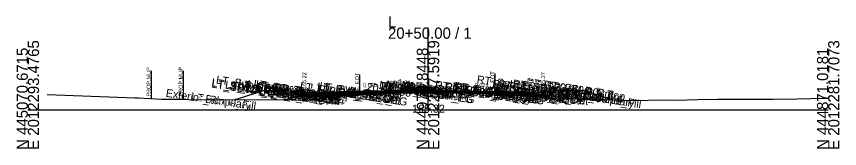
# Model space of a CAD drawing. Extents: x -26 to 4203, y -10 to 9526.
# Drawn here: x 997.2 to 1202.8, y 490.3 to 523.5 of the extents above; entities that cross this region are included whole.
import ezdxf

# ---------------------------------------------------------------- set-up
doc = ezdxf.new("R2010")
doc.units = 0
for name, color, linetype in [('Default', 7, 'Continuous'), ('Exist CMT Pavement', 7, 'Continuous'), ('Exist Cross Section Cell', 7, 'Continuous'), ('Exist XS Center Line Elevation Label', 7, 'Continuous'), ('Exist XS Ground Line', 7, 'Continuous'), ('Prop CMT Conc Surface', 7, 'Continuous'), ('Prop CMT Concrete Structures', 7, 'Continuous'), ('Prop CMT Pvmt Course 1', 7, 'Continuous'), ('Prop CMT Pvmt Course 1 CG', 7, 'Continuous'), ('Prop CMT Pvmt Course 1 Wedge', 7, 'Continuous'), ('Prop CMT Pvmt Course 2', 7, 'Continuous'), ('Prop CMT Pvmt Course 2 Wedge', 7, 'Continuous'), ('Prop CMT Pvmt Course 3', 7, 'Continuous'), ('Prop CMT Pvmt Course 3 Wedge', 7, 'Continuous'), ('Prop CMT Pvmt Surface', 7, 'Continuous'), ('Prop CMT Pvmt Wedge Surface 1', 7, 'Continuous'), ('Prop CMT Pvmt Wedge Surface 2', 7, 'Continuous'), ('Prop CMT Pvmt Wedge Surface 3', 7, 'Continuous'), ('Prop CMT Slope Grass', 7, 'Continuous'), ('Prop CMT Subgrade Earthwork', 7, 'Continuous'), ('Prop XS Hydro Elevations', 7, 'Continuous'), ('Prop XS Label Text', 7, 'Continuous'), ('Prop XS SE Text', 7, 'Continuous'), ('Prop XS Side Slope Text', 7, 'Continuous'), ('Scratch_Level_0', 7, 'Continuous')]:
    doc.layers.add(name, color=color, linetype=linetype)

msp = doc.modelspace()

# ---------------------------------------------------------------- linework, layer by layer
at = {"layer": 'Exist CMT Pavement'}
for points in [[(1100, 504.32), (1098.93, 504.32), (1098.29, 504.32), (1096.56, 504.29), (1095.78, 504.28), (1094.34, 504.26), (1093.69, 504.26), (1093.52, 504.26), (1093.28, 504.25), (1092.26, 504.21), (1090.78, 504.15), (1089.59, 504.1), (1088.28, 504.05), (1087.1, 503.97), (1085.76, 503.87), (1084.71, 503.85), (1082.9, 503.79)], [(1100, 504.32), (1100.79, 504.32), (1101.29, 504.32), (1103.29, 504.32), (1103.62, 504.32), (1104.82, 504.32), (1105.68, 504.31), (1105.79, 504.31), (1106.01, 504.31), (1108.3, 504.27), (1108.37, 504.27), (1109.65, 504.26), (1110.81, 504.24), (1110.88, 504.24), (1113.32, 504.19), (1113.56, 504.19), (1115.82, 504.14), (1115.89, 504.14), (1116.71, 504.14)], [(1082.9, 503.79), (1082.9, 503.79)]]:
    msp.add_lwpolyline(points, dxfattribs=at)
at = {"layer": 'Exist Cross Section Cell'}
for p, q in [((1100, 500), (1100, 520.65)), ((1000, 500), (1100, 500)), ((1100, 500), (1200, 500))]:
    msp.add_line(p, q, dxfattribs=at)
at = {"layer": 'Exist XS Ground Line'}
msp.add_lwpolyline([(1004.81, 503.84), (1026.81, 503.01), (1027.6, 503), (1033.38, 502.73), (1038.28, 502.67), (1040.26, 502.64), (1065.9, 502.52), (1068.93, 502.44), (1069.48, 502.47), (1071.16, 502.65), (1074.84, 503.03), (1081.1, 503.68), (1082.9, 503.79), (1084.71, 503.85), (1085.76, 503.87), (1087.1, 503.97), (1088.28, 504.05), (1089.59, 504.1), (1090.78, 504.15), (1092.26, 504.21), (1093.69, 504.26), (1094.34, 504.26), (1095.78, 504.28), (1096.56, 504.29), (1098.29, 504.32), (1098.93, 504.32), (1100, 504.32), (1100.79, 504.32), (1101.29, 504.32), (1103.29, 504.32), (1103.62, 504.32), (1104.82, 504.32), (1106.01, 504.31), (1108.37, 504.27), (1109.65, 504.26), (1110.88, 504.24), (1113.56, 504.19), (1115.89, 504.14), (1116.71, 504.14), (1125, 503.43), (1132.16, 502.87), (1138.93, 502.78), (1142.17, 502.7), (1148.39, 502.41), (1152.19, 502.34), (1157.85, 502.51), (1162.21, 502.47), (1167.31, 502.58), (1172.23, 502.74), (1176.77, 502.74), (1182.25, 502.69), (1186.23, 502.68), (1192.27, 502.8), (1195.69, 502.89), (1200, 502.95)], dxfattribs=at)
at = {"layer": 'Prop CMT Conc Surface'}
for points in [[(1069.06, 504.22), (1069.06, 504.72), (1068.56, 504.72)], [(1071.06, 504.35), (1069.06, 504.22)], [(1126.75, 504.4), (1128.75, 504.27)], [(1128.75, 504.27), (1128.75, 504.77), (1129.25, 504.77)], [(1133.25, 504.86), (1138.25, 504.96)]]:
    msp.add_lwpolyline(points, dxfattribs=at)
at = {"layer": 'Prop CMT Concrete Structures'}
for points in [[(1071.06, 504.35), (1069.06, 504.22), (1069.06, 504.72), (1068.56, 504.72)], [(1068.56, 504.72), (1068.56, 503.7), (1071.06, 503.76)], [(1071.06, 503.76), (1071.06, 504.35)], [(1102, 505.02), (1101.99, 505.19), (1101.24, 505.44), (1098.92, 505.48), (1096.59, 505.38), (1095.84, 505.13), (1095.83, 504.96)], [(1095.83, 504.96), (1100, 505.07), (1102, 505.02)], [(1126.75, 504.4), (1128.75, 504.27), (1128.75, 504.77), (1129.25, 504.77)], [(1129.25, 504.77), (1129.25, 503.76), (1126.75, 503.82)], [(1126.75, 503.82), (1126.75, 504.4)], [(1138.25, 504.96), (1133.25, 504.86)], [(1133.25, 504.86), (1133.25, 504.53)], [(1133.25, 504.53), (1138.25, 504.63)], [(1138.25, 504.63), (1138.25, 504.96)]]:
    msp.add_lwpolyline(points, dxfattribs=at)
at = {"layer": 'Prop CMT Pvmt Course 1'}
for points in [[(1100, 505.07), (1071.06, 504.35)], [(1071.06, 504.1), (1082.9, 504.39)], [(1071.06, 504.35), (1071.06, 504.1)], [(1082.9, 504.52), (1100, 504.94)], [(1082.9, 504.39), (1082.9, 504.52)], [(1100, 504.82), (1100, 505.07)], [(1100, 505.07), (1126.75, 504.4)], [(1100, 504.82), (1100, 505.07)], [(1100, 504.94), (1100, 504.82), (1100, 504.82)], [(1116.71, 504.53), (1100, 504.94)], [(1100, 504.94), (1100, 504.82), (1100, 504.82)], [(1116.71, 504.4), (1116.71, 504.53)], [(1126.75, 504.15), (1116.71, 504.4)], [(1126.75, 504.4), (1126.75, 504.15)]]:
    msp.add_lwpolyline(points, dxfattribs=at)
at = {"layer": 'Prop CMT Pvmt Course 1 CG'}
for points in [[(1071.06, 503.76), (1068.06, 503.69), (1067.72, 503.35)], [(1067.72, 503.35), (1071.06, 503.43)], [(1071.06, 503.43), (1071.06, 503.76)], [(1126.75, 503.82), (1129.75, 503.74), (1130.09, 503.4)], [(1126.75, 503.48), (1126.75, 503.82)], [(1130.09, 503.4), (1126.75, 503.48)]]:
    msp.add_lwpolyline(points, dxfattribs=at)
at = {"layer": 'Prop CMT Pvmt Course 1 Wedge'}
for points in [[(1082.9, 504.52), (1083, 504.52), (1084.71, 504.56), (1085.76, 504.59), (1087.1, 504.62), (1088.28, 504.65), (1089.59, 504.68), (1090.78, 504.71), (1092.26, 504.75), (1093.28, 504.78), (1093.52, 504.78), (1093.69, 504.79), (1094.34, 504.8), (1095.78, 504.84), (1096.56, 504.86), (1098.29, 504.9), (1098.93, 504.92), (1100, 504.94)], [(1100, 504.82), (1098.93, 504.79), (1098.29, 504.78), (1096.56, 504.73), (1095.78, 504.71), (1094.34, 504.68), (1093.69, 504.66), (1093.52, 504.66), (1093.28, 504.65), (1092.26, 504.63), (1090.78, 504.59), (1089.59, 504.56), (1088.28, 504.53), (1087.1, 504.5), (1085.76, 504.46), (1084.71, 504.44), (1083, 504.39), (1082.9, 504.39)], [(1082.9, 504.52), (1082.9, 504.52)], [(1082.9, 504.39), (1082.9, 504.52)], [(1082.9, 504.39), (1082.9, 504.39)], [(1100, 504.94), (1100, 504.82)], [(1100, 504.94), (1100.79, 504.92), (1101.29, 504.91), (1103.29, 504.86), (1103.62, 504.85), (1104.82, 504.82), (1105.68, 504.8), (1105.79, 504.8), (1106.01, 504.79), (1108.3, 504.74), (1108.37, 504.74), (1109.65, 504.7), (1110.81, 504.67), (1110.88, 504.67), (1113.32, 504.61), (1113.56, 504.61), (1115.82, 504.55), (1115.89, 504.55), (1116.71, 504.53)], [(1100, 504.82), (1100, 504.94)], [(1116.71, 504.4), (1115.89, 504.42), (1115.82, 504.42), (1113.56, 504.48), (1113.32, 504.49), (1110.88, 504.55), (1110.81, 504.55), (1109.65, 504.58), (1108.37, 504.61), (1108.3, 504.61), (1106.01, 504.67), (1105.79, 504.67), (1105.68, 504.68), (1104.82, 504.7), (1103.62, 504.73), (1103.29, 504.74), (1101.29, 504.79), (1100.79, 504.8), (1100, 504.82)], [(1116.71, 504.53), (1116.71, 504.4)]]:
    msp.add_lwpolyline(points, dxfattribs=at)
at = {"layer": 'Prop CMT Pvmt Course 2'}
for points in [[(1082.9, 504.39), (1071.06, 504.1)], [(1071.06, 504.1), (1071.06, 503.76)], [(1071.06, 503.76), (1082.9, 504.06)], [(1082.9, 504.06), (1082.9, 504.39)], [(1116.71, 504.07), (1116.71, 504.4)], [(1116.71, 504.4), (1126.75, 504.15)], [(1126.75, 503.82), (1116.71, 504.07)], [(1126.75, 504.15), (1126.75, 503.82)]]:
    msp.add_lwpolyline(points, dxfattribs=at)
at = {"layer": 'Prop CMT Pvmt Course 2 Wedge'}
for points in [[(1082.9, 504.39), (1083, 504.39), (1084.71, 504.44), (1085.76, 504.46), (1087.1, 504.5), (1088.28, 504.53), (1089.59, 504.56), (1090.78, 504.59), (1092.26, 504.63), (1093.28, 504.65), (1093.52, 504.66), (1093.69, 504.66), (1094.34, 504.68), (1095.78, 504.71), (1096.56, 504.73), (1098.29, 504.78), (1098.93, 504.79), (1100, 504.82)], [(1100, 504.49), (1098.93, 504.46), (1098.29, 504.44), (1096.56, 504.4), (1095.78, 504.38), (1094.34, 504.34), (1093.69, 504.33), (1093.52, 504.32), (1093.28, 504.32), (1092.26, 504.29), (1090.78, 504.26), (1089.59, 504.23), (1088.28, 504.19), (1087.1, 504.16), (1085.76, 504.13), (1084.71, 504.1), (1083, 504.06), (1082.9, 504.06)], [(1082.9, 504.39), (1082.9, 504.39)], [(1082.9, 504.06), (1082.9, 504.39)], [(1082.9, 504.06), (1082.9, 504.06)], [(1100, 504.82), (1100.79, 504.8), (1101.29, 504.79), (1103.29, 504.74), (1103.62, 504.73), (1104.82, 504.7), (1105.68, 504.68), (1105.79, 504.67), (1106.01, 504.67), (1108.3, 504.61), (1108.37, 504.61), (1109.65, 504.58), (1110.81, 504.55), (1110.88, 504.55), (1113.32, 504.49), (1113.56, 504.48), (1115.82, 504.42), (1115.89, 504.42), (1116.71, 504.4)], [(1100, 504.49), (1100, 504.82)], [(1100, 504.82), (1100, 504.49)], [(1116.71, 504.14), (1115.89, 504.14), (1115.82, 504.14), (1113.56, 504.19), (1113.32, 504.19), (1110.88, 504.24), (1110.81, 504.24), (1109.65, 504.26), (1108.94, 504.26), (1108.37, 504.28), (1108.3, 504.28), (1106.01, 504.34), (1105.79, 504.34), (1105.68, 504.34), (1104.82, 504.37), (1103.62, 504.4), (1103.29, 504.4), (1101.29, 504.45), (1100.79, 504.47), (1100, 504.49)], [(1116.71, 504.4), (1116.71, 504.14)]]:
    msp.add_lwpolyline(points, dxfattribs=at)
at = {"layer": 'Prop CMT Pvmt Course 3'}
for points in [[(1082.9, 504.06), (1071.06, 503.76)], [(1082.9, 503.72), (1082.9, 504.06)], [(1116.71, 504.07), (1126.75, 503.82)], [(1116.71, 503.74), (1116.71, 504.07)], [(1071.06, 503.76), (1071.06, 503.43)], [(1071.06, 503.43), (1082.9, 503.72)], [(1126.75, 503.48), (1116.71, 503.74)], [(1126.75, 503.82), (1126.75, 503.48)]]:
    msp.add_lwpolyline(points, dxfattribs=at)
at = {"layer": 'Prop CMT Pvmt Course 3 Wedge'}
for points in [[(1082.9, 504.06), (1083, 504.06), (1084.71, 504.1), (1085.76, 504.13), (1087.1, 504.16), (1088.28, 504.19), (1089.59, 504.23), (1090.78, 504.26), (1092.26, 504.29), (1093.28, 504.32), (1093.52, 504.32), (1093.69, 504.33), (1094.34, 504.34), (1095.78, 504.38), (1096.56, 504.4), (1098.29, 504.44), (1098.93, 504.46), (1100, 504.49)], [(1100, 504.32), (1098.93, 504.32), (1098.29, 504.32), (1096.56, 504.29), (1095.78, 504.28), (1094.34, 504.26), (1093.69, 504.26), (1093.52, 504.26), (1093.28, 504.25), (1092.26, 504.21), (1090.78, 504.15), (1089.59, 504.1), (1088.28, 504.05), (1087.1, 503.97), (1085.76, 503.87), (1084.71, 503.85), (1082.9, 503.79)], [(1082.9, 504.06), (1082.9, 504.06)], [(1082.9, 503.79), (1082.9, 504.06)], [(1100, 504.49), (1100.79, 504.47), (1101.29, 504.45), (1103.29, 504.4), (1103.62, 504.4), (1104.82, 504.37), (1105.68, 504.34), (1105.79, 504.34), (1106.01, 504.34), (1108.3, 504.28), (1108.37, 504.28), (1108.93, 504.26)], [(1100, 504.32), (1100, 504.49)], [(1100, 504.49), (1100, 504.32)], [(1108.93, 504.26), (1108.37, 504.27), (1108.3, 504.27), (1106.01, 504.31), (1105.79, 504.31), (1105.68, 504.31), (1104.82, 504.32), (1103.62, 504.32), (1103.29, 504.32), (1101.29, 504.32), (1100.79, 504.32), (1100, 504.32)], [(1082.9, 503.79), (1082.9, 503.79)]]:
    msp.add_lwpolyline(points, dxfattribs=at)
at = {"layer": 'Prop CMT Pvmt Surface'}
for points in [[(1100, 505.07), (1071.06, 504.35)], [(1100, 505.07), (1126.75, 504.4)]]:
    msp.add_lwpolyline(points, dxfattribs=at)
at = {"layer": 'Prop CMT Pvmt Wedge Surface 1'}
for points in [[(1082.9, 504.39), (1071.06, 504.1)], [(1071.06, 504.1), (1071.06, 504.35)], [(1100, 504.94), (1082.9, 504.52)], [(1082.9, 504.52), (1082.9, 504.39)], [(1100, 504.94), (1116.71, 504.53)], [(1116.71, 504.53), (1116.71, 504.4)], [(1116.71, 504.4), (1126.75, 504.15)], [(1126.75, 504.15), (1126.75, 504.4)]]:
    msp.add_lwpolyline(points, dxfattribs=at)
at = {"layer": 'Prop CMT Pvmt Wedge Surface 2'}
for points in [[(1100, 504.82), (1071.06, 504.1)], [(1071.06, 504.1), (1071.06, 504.35)], [(1100, 504.82), (1126.75, 504.15)], [(1126.75, 504.15), (1126.75, 504.4)]]:
    msp.add_lwpolyline(points, dxfattribs=at)
at = {"layer": 'Prop CMT Pvmt Wedge Surface 3'}
for points in [[(1100, 504.49), (1071.06, 503.76)], [(1071.06, 503.76), (1071.06, 504.35)], [(1100, 504.49), (1126.75, 503.82)], [(1126.75, 503.82), (1126.75, 504.4)]]:
    msp.add_lwpolyline(points, dxfattribs=at)
at = {"layer": 'Prop CMT Slope Grass'}
for points in [[(1068.56, 504.72), (1059.06, 504.91), (1052.1, 502.59)], [(1129.25, 504.77), (1138.75, 504.96), (1146.09, 502.52)]]:
    msp.add_lwpolyline(points, dxfattribs=at)
at = {"layer": 'Prop CMT Subgrade Earthwork'}
for points in [[(1071.06, 503.43), (1067.72, 503.35), (1066.3, 504.76)], [(1116.71, 503.74), (1116.71, 504.14)], [(1126.75, 503.48), (1130.09, 503.4), (1131.51, 504.82)], [(1082.9, 503.72), (1071.06, 503.43)], [(1082.9, 503.72), (1082.9, 503.79)], [(1116.71, 503.74), (1126.75, 503.48)]]:
    msp.add_lwpolyline(points, dxfattribs=at)
at = {"layer": 'Prop XS Label Text'}
for p, q in [((1030.79, 509.78), (1030.79, 502.78)), ((1038.81, 509.8), (1038.81, 502.8)), ((1082.9, 508.79), (1082.9, 503.79)), ((1116.71, 509.14), (1116.71, 504.14))]:
    msp.add_line(p, q, dxfattribs=at)

# ---------------------------------------------------------------- texts
at = {"layer": 'Default'}
msp.add_text('-', height=0.0001, dxfattribs=at).set_placement((1000, 500))
at = {"layer": 'Exist Cross Section Cell'}
for s, p in [('L', (1090, 520.65)), ('20+50.00 / 1', (1090, 517.85))]:
    msp.add_text(s, height=2.8, dxfattribs=at).set_placement(p)
for s, p in [('E 2012293.4765', (1002.8, 490)), ('E 2012287.5919', (1102.8, 490)), ('E 2012281.7073', (1202.8, 490)), ('N 445070.6715', (1000, 490)), ('N 444970.8448', (1100, 490)), ('N 444871.0181', (1200, 490))]:
    msp.add_text(s, height=2.8, rotation=90, dxfattribs=at).set_placement(p)
at = {"layer": 'Exist XS Center Line Elevation Label'}
msp.add_text('165.32', height=2, dxfattribs=at).set_placement((1096.03, 499.32))
at = {"layer": 'Prop XS Hydro Elevations'}
for s, p in [('165.22', (1069.56, 505.22)), ('165.27', (1129.25, 505.27))]:
    msp.add_text(s, height=1, rotation=90, dxfattribs=at).set_placement(p)
at = {"layer": 'Prop XS Label Text'}
for s, p in [('PROP.MUP', (1030.69, 503.35)), ('PROP.MUP', (1038.71, 503.37)), ('E. EOT', (1082.8, 504.81)), ('E. EOT', (1116.61, 505.16))]:
    msp.add_text(s, height=1, rotation=90, dxfattribs=at).set_placement(p)
at = {"layer": 'Prop XS SE Text'}
for rotation, p in [(1.4312, (1083.77, 505.66)), (358.5695, (1111.67, 505.78))]:
    msp.add_text('0.025', height=1, rotation=rotation, dxfattribs=at).set_placement(p)
at = {"layer": 'Prop XS Side Slope Text'}
for rotation, p in [(18.4361, (1053.65, 503.89)), (341.5644, (1141.9, 504.7))]:
    msp.add_text('3:1', height=1, rotation=rotation, dxfattribs=at).set_placement(p)
at = {"layer": 'Scratch_Level_0'}
for s, p in [('LT_Sub_Trench_Out_DLT', (1046.94, 506.65)), ('RT_Sub_Trench_Out_DLT', (1112.09, 506.72)), ('LT_SDWK_Out_Top', (1045.8, 505.96)), ('LT_SDWK_Out_Bot', (1045.83, 505.62)), ('LT_CSLP_Pnt', (1049.19, 505.37)), ('LT_SDWK_In_Top', (1052.4, 505.62)), ('LT_SDWK_In_Bot', (1052.43, 505.28)), ('LT_CG1_Shelf_Out', (1054.61, 504.69)), ('LT_CG_Top_Face', (1056.31, 505.62)), ('LT_CG_Top_BOC', (1056.83, 505.47)), ('LT_CG_Bot_BOC', (1056.86, 504.44)), ('LT_CG_Top_Gut', (1057.28, 504.97)), ('LT_CG_Bot_IE', (1060.94, 504.27)), ('LT_PV2_OEOT', (1061.2, 504.56)), ('LT_PV3_OEOT', (1061.2, 504.23)), ('LT_PV1_OEOT', (1061.76, 504.73)), ('20+50.00', (1062.15, 504.5)), ('20+50.00', (1063.53, 504.33)), ('LT_PV_Sub_Tie_Out', (1067.88, 505.03)), ('LT_PV_OEEOP_EG', (1070.43, 504.65)), ('LT_Sub_OEEOP', (1072.08, 504.34)), ('LT_PV2_OEEOP', (1072.18, 504.99)), ('LT_PV3_OEEOP', (1072.18, 504.66)), ('LT_PV1_OEEOP', (1072.74, 505.03)), ('20+50.00', (1084.55, 504.88)), ('MI_Face In', (1087.67, 505.35)), ('RT_PV_IEEOP_EG', (1088.12, 505.09)), ('LT_PV_IEEOP_EG', (1088.17, 505.08)), ('MI_Bot In', (1088.65, 505.03)), ('MI_Top In', (1089.38, 505.45)), ('RT_PV2_IEEOP', (1089.87, 505.33)), ('RT_PV3_IEEOP', (1089.87, 504.99)), ('LT_PV2_IEEOP', (1089.92, 505.32)), ('LT_PV3_IEEOP', (1089.92, 504.99)), ('RT_PV1_IEEOP', (1090.43, 505.37)), ('LT_PV1_IEEOP', (1090.48, 505.36)), ('20+50.00', (1090.7, 505.45)), ('MI_Crown', (1091.92, 505.52)), ('MI_Face Out', (1092.22, 505.64)), ('MI_Top Out', (1092.42, 505.75)), ('MI_Bot Out', (1093.21, 505.33)), ('PV2_PGL', (1093.82, 504.73)), ('PV1_PGL', (1094.39, 504.9)), ('20+50.00', (1095.09, 505.11)), ('MI_Bot', (1095.09, 504.79)), ('RT_PV_Sub_Tie_Out', (1101.61, 505.39)), ('RT_PV_OEEOP_EG', (1104.19, 505)), ('20+50.00', (1104.48, 504.81)), ('RT_Sub_OEEOP', (1105.84, 504.35)), ('RT_PV2_OEEOP', (1105.94, 505.01)), ('RT_PV3_OEEOP', (1105.94, 504.67)), ('RT_PV1_OEEOP', (1106.5, 505.05)), ('RT_CG_Top_Face', (1115.96, 505.68)), ('RT_CG1_Shelf_Out', (1116.26, 504.75)), ('RT_CG_Bot_IE', (1116.58, 504.33)), ('RT_PV2_OEOT', (1116.84, 504.63)), ('RT_PV3_OEOT', (1116.84, 504.29)), ('RT_CG_Top_Gut', (1116.92, 505.03)), ('RT_PV1_OEOT', (1117.4, 504.79)), ('RT_CG_Top_BOC', (1117.47, 505.53)), ('RT_CG_Bot_BOC', (1117.5, 504.51)), ('RT_SDWK_In_Top', (1121.05, 505.68)), ('RT_SDWK_In_Bot', (1121.08, 505.34)), ('20+50.00', (1121.42, 504.32)), ('20+50.00', (1121.86, 504.8)), ('RT_SDWK_Out_Top', (1124.44, 506.02)), ('RT_SDWK_Out_Bot', (1124.47, 505.68)), ('20+50.00', (1125.46, 504.86)), ('RT_CSLP_Pnt', (1128.84, 505.44)), ('20+50.00', (1131.35, 504.99)), ('Exterior Boundary', (1034.38, 503.32)), ('LT_Slope_Fill', (1040.69, 502.37)), ('LT_Sub_OEOP', (1057.79, 503.82)), ('LT_Sub_OEOT', (1061.1, 503.91)), ('RT_Sub_OEOT', (1116.74, 503.97)), ('RT_Sub_OEOP', (1120.12, 503.89)), ('Exterior Boundary', (1130.25, 503.88)), ('RT_Slope_Fill', (1136.52, 502.94))]:
    msp.add_text(s, height=2, rotation=351.4697, dxfattribs=at).set_placement(p)

doc.saveas('drawing.dxf')
